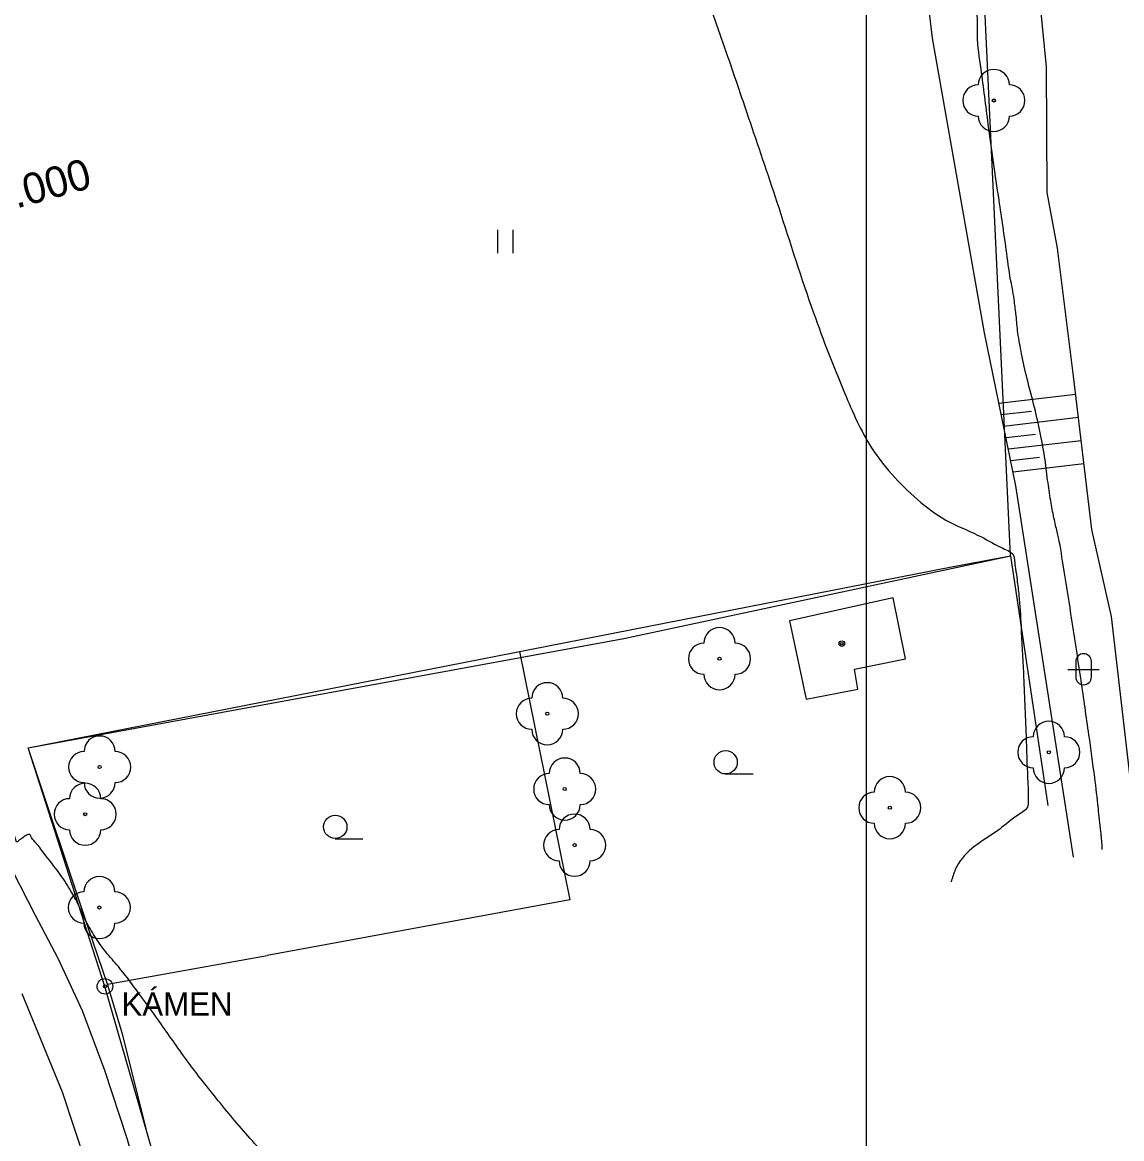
# Model space of a CAD drawing. Extents: x -478102 to -473059, y -1117705 to -1114104.
# Drawn here: x -476236.6 to -476165.9, y -1117156 to -1117084.2 of the extents above; entities that cross this region are included whole.
import ezdxf

# ---------------------------------------------------------------- set-up
doc = ezdxf.new("R2010")
doc.units = 0
for name, color, linetype in [('BodoveZnackySloupy', 7, 'Continuous'), ('Budovy', 7, 'Continuous'), ('cestn___p____kop_n__vrh', 7, 'Continuous'), ('HladinaVodnihoToku', 7, 'Continuous'), ('HranaTerennihoUtvaru', 7, 'Continuous'), ('ObPÚ', 7, 'Continuous'), ('Ploty', 7, 'Continuous'), ('POLYGONY_SITUACE_PF_POPISY', 7, 'Continuous'), ('PopisnaZnackaVyhybka', 7, 'Continuous'), ('PopisneZnackyKultura', 7, 'Continuous'), ('PopisObjektu', 7, 'Continuous'), ('RozhraniVozovky', 7, 'Continuous'), ('Teren_HranaSvahu', 7, 'Continuous'), ('Vrstevnice_hlavni', 7, 'Continuous'), ('Vrstevnice_vedlejsi', 7, 'Continuous'), ('VstupNaPozemek', 7, 'Continuous'), ('VyskoveSrafy', 7, 'Continuous'), ('ZnackyStromu', 7, 'Continuous')]:
    doc.layers.add(name, color=color, linetype=linetype)

msp = doc.modelspace()

# ---------------------------------------------------------------- linework, layer by layer
at = {"layer": 'BodoveZnackySloupy'}
for radius in [0.5, 0.1]:
    msp.add_circle((-476231.32, -1117146.23), radius, dxfattribs=at)
at = {"layer": 'Budovy'}
msp.add_lwpolyline([(-476179.82, -1117125.147), (-476180.599, -1117121.234), (-476187.275, -1117122.701), (-476186.207, -1117127.742), (-476182.873, -1117127.103), (-476183.091, -1117125.822)], close=True, dxfattribs=at)
at = {"layer": 'cestn___p____kop_n__vrh'}
msp.add_lwpolyline([(-476182.335, -1117180.282), (-476602.335, -1117180.282), (-476602.335, -1116586.282), (-476182.335, -1116586.282)], close=True, dxfattribs=at)
at = {"layer": 'HladinaVodnihoToku'}
msp.add_lwpolyline([(-476165.052, -1117135.383), (-476166.552, -1117122.432), (-476167.831, -1117116.835), (-476168.995, -1117106.978), (-476170.029, -1117098.738), (-476170.701, -1117095.145), (-476170.746, -1117087.056), (-476171.949, -1117074.832), (-476173.391, -1117070.652), (-476173.059, -1117068.741), (-476173.366, -1117065.264), (-476174.142, -1117057.395), (-476175.337, -1117045.193), (-476176.15, -1117036.518), (-476177.362, -1117031.476), (-476176.964, -1117029.141), (-476177.777, -1117025.659), (-476180.222, -1117017.465), (-476181.969, -1117010.204)], dxfattribs=at)
at = {"layer": 'HranaTerennihoUtvaru'}
msp.add_lwpolyline([(-476178.08, -1117085.22), (-476182.65, -1117046.23), (-476184.28, -1117024.06), (-476194.45, -1117027.03)], dxfattribs=at)
at = {"layer": 'ObPÚ'}
msp.add_lwpolyline([(-476159.5, -1117192.77), (-476224.13, -1117203.13), (-476225.41, -1117191.08), (-476226.67, -1117162.34), (-476231.32, -1117146.23), (-476236.27, -1117130.89), (-476197.93, -1117123.85), (-476173.05, -1117118.52), (-476175.07, -1117075.48), (-476185.89, -1117036.74), (-476189.59, -1117026.33), (-476192, -1117018.92), (-476203.93, -1116985.93)], dxfattribs=at)
at = {"layer": 'Ploty'}
for p, q in [((-476173.05, -1117118.52), (-476170.664, -1117134.589)), ((-476204.648, -1117124.689), (-476201.416, -1117140.657)), ((-476201.416, -1117140.657), (-476220.878, -1117144.236)), ((-476231.16, -1117146.08), (-476220.878, -1117144.236))]:
    msp.add_line(p, q, dxfattribs=at)
for points in [[(-476236.27, -1117130.89), (-476176.96, -1117119.26), (-476173.05, -1117118.52)], [(-476232.38, -1117142.5), (-476236.27, -1117130.89)], [(-476230.16, -1117149.36), (-476231.16, -1117146.08)]]:
    msp.add_lwpolyline(points, dxfattribs=at)
at = {"layer": 'PopisnaZnackaVyhybka'}
for radius in [0.18, 0.0797]:
    msp.add_circle((-476183.909, -1117124.176), radius, dxfattribs=at)
at = {"layer": 'PopisneZnackyKultura'}
for p, q in [((-476206.051, -1117099.044), (-476206.051, -1117097.544)), ((-476205.051, -1117099.044), (-476205.051, -1117097.544)), ((-476168.864, -1117125.331), (-476168.864, -1117126.331)), ((-476167.864, -1117125.331), (-476167.864, -1117126.331)), ((-476169.364, -1117125.831), (-476167.364, -1117125.831)), ((-476191.384, -1117132.551), (-476189.624, -1117132.551)), ((-476216.498, -1117136.728), (-476214.738, -1117136.728))]:
    msp.add_line(p, q, dxfattribs=at)
for centre in [(-476191.384, -1117131.811), (-476216.498, -1117135.968)]:
    msp.add_circle(centre, 0.75, dxfattribs=at)
for centre, start, end in [((-476168.356, -1117125.324), 0, 180), ((-476168.356, -1117126.324), 180, 0)]:
    msp.add_arc(centre, 0.5, start, end, dxfattribs=at)
at = {"layer": 'RozhraniVozovky'}
for points in [[(-476237.801, -1117137.737), (-476235.804, -1117141.64), (-476234.344, -1117144.407), (-476232.794, -1117147.784), (-476231.339, -1117151.616), (-476229.905, -1117155.995), (-476228.676, -1117160.384)], [(-476232.539, -1117157.584), (-476234.044, -1117153.045), (-476236.653, -1117146.701)]]:
    msp.add_lwpolyline(points, dxfattribs=at)
at = {"layer": 'Teren_HranaSvahu'}
for p, q in [((-476174.722, -1117104.178), (-476178.08, -1117085.22)), ((-476172.711, -1117114.033), (-476174.722, -1117104.178)), ((-476168.996, -1117137.921), (-476172.711, -1117114.033))]:
    msp.add_line(p, q, dxfattribs=at)
at = {"layer": 'Vrstevnice_hlavni'}
msp.add_spline([(-476206.652, -1117178.906), (-476206.912, -1117178.348), (-476209.341, -1117173.725), (-476211.536, -1117169.856), (-476213.496, -1117166.739), (-476215.223, -1117164.376), (-476216.372, -1117162.765), (-476216.944, -1117161.906), (-476216.939, -1117161.798), (-476216.948, -1117161.695), (-476216.97, -1117161.597), (-476217.006, -1117161.504), (-476217.035, -1117161.434), (-476217.055, -1117161.387), (-476217.068, -1117161.364), (-476217.869, -1117160.487), (-476219.458, -1117158.755), (-476221.836, -1117156.168), (-476224.025, -1117153.59), (-476226.026, -1117151.021), (-476227.839, -1117148.461), (-476229.316, -1117146.439), (-476230.458, -1117144.956), (-476231.265, -1117144.011), (-476231.967, -1117143.022), (-476232.564, -1117141.99), (-476233.057, -1117140.915), (-476233.666, -1117139.839), (-476234.391, -1117138.762), (-476235.231, -1117137.684), (-476235.806, -1117136.941), (-476236.117, -1117136.531), (-476236.162, -1117136.455), (-476236.279, -1117136.467), (-476236.468, -1117136.566), (-476236.728, -1117136.753), (-476236.903, -1117136.876), (-476236.994, -1117136.936), (-476237.001, -1117136.931), (-476237.008, -1117136.923), (-476237.014, -1117136.912), (-476237.021, -1117136.898), (-476237.036, -1117136.855), (-476237.059, -1117136.783), (-476237.089, -1117136.682), (-476237.266, -1117136.022), (-476237.588, -1117134.805), (-476238.057, -1117133.03), (-476238.423, -1117131.552), (-476238.688, -1117130.371), (-476238.85, -1117129.488), (-476238.979, -1117128.769), (-476239.073, -1117128.213), (-476239.134, -1117127.822), (-476239.32, -1117127.303), (-476239.632, -1117126.656), (-476240.07, -1117125.882), (-476240.487, -1117125.12), (-476240.885, -1117124.371), (-476241.262, -1117123.634), (-476241.579, -1117122.995), (-476241.836, -1117122.453), (-476242.033, -1117122.009), (-476242.251, -1117121.588), (-476242.49, -1117121.19), (-476242.749, -1117120.815), (-476243.08, -1117120.066), (-476243.481, -1117118.944), (-476243.953, -1117117.449), (-476244.291, -1117116.381), (-476244.494, -1117115.74), (-476244.561, -1117115.526), (-476244.665, -1117115.217), (-476244.806, -1117114.813), (-476244.984, -1117114.313), (-476245.236, -1117113.882), (-476245.562, -1117113.52), (-476245.962, -1117113.226), (-476246.483, -1117112.711), (-476247.125, -1117111.974), (-476247.888, -1117111.015), (-476248.249, -1117110.238), (-476248.209, -1117109.642), (-476247.766, -1117109.227), (-476247.681, -1117108.981), (-476247.952, -1117108.903), (-476248.581, -1117108.994), (-476249.094, -1117108.824), (-476249.493, -1117108.392)], degree=3, dxfattribs=at)
at = {"layer": 'Vrstevnice_vedlejsi'}
for points in [[(-476218.662, -1117033.435), (-476218.822, -1117034.635), (-476217.263, -1117036.911), (-476213.986, -1117040.265), (-476208.992, -1117044.695), (-476205.309, -1117047.877), (-476202.938, -1117049.809), (-476201.877, -1117050.493), (-476201.083, -1117050.788), (-476200.555, -1117050.695), (-476200.293, -1117050.212), (-476200.099, -1117049.847), (-476199.974, -1117049.597), (-476199.917, -1117049.464), (-476199.835, -1117049.37), (-476199.726, -1117049.313), (-476199.592, -1117049.295), (-476199.387, -1117049.198), (-476199.112, -1117049.021), (-476198.765, -1117048.765), (-476198.307, -1117048.409), (-476197.736, -1117047.953), (-476197.054, -1117047.397), (-476196.575, -1117047.173), (-476196.299, -1117047.28), (-476196.227, -1117047.719), (-476196.128, -1117048.519), (-476196.001, -1117049.68), (-476195.846, -1117051.202), (-476195.702, -1117052.674), (-476195.567, -1117054.097), (-476195.442, -1117055.471), (-476195.474, -1117056.701), (-476195.663, -1117057.787), (-476196.008, -1117058.731), (-476196.365, -1117059.696), (-476196.731, -1117060.685), (-476197.109, -1117061.695), (-476197.123, -1117063.752), (-476196.775, -1117066.855), (-476196.063, -1117071.005), (-476195.366, -1117074.361), (-476194.682, -1117076.923), (-476194.013, -1117078.692), (-476193.219, -1117080.86), (-476192.302, -1117083.427), (-476191.26, -1117086.392), (-476189.817, -1117090.625), (-476187.973, -1117096.125), (-476185.729, -1117102.894), (-476183.735, -1117108.045), (-476181.992, -1117111.578), (-476180.498, -1117113.494), (-476178.823, -1117115.088), (-476176.965, -1117116.361), (-476174.925, -1117117.312), (-476173.551, -1117118.042), (-476172.843, -1117118.55), (-476172.8, -1117118.837), (-476172.731, -1117119.351), (-476172.637, -1117120.093), (-476172.517, -1117121.062), (-476172.381, -1117123.052), (-476172.229, -1117126.063), (-476172.059, -1117130.096), (-476171.954, -1117132.864), (-476171.913, -1117134.367), (-476171.937, -1117134.606), (-476172.55, -1117135.185), (-476173.752, -1117136.105), (-476175.544, -1117137.365), (-476176.609, -1117138.711), (-476176.875, -1117139.506)], [(-476167.154, -1117137.424), (-476167.161, -1117137.225), (-476167.247, -1117136.247), (-476167.406, -1117134.768), (-476167.64, -1117132.789), (-476168.012, -1117130.045), (-476168.521, -1117126.535), (-476169.167, -1117122.259), (-476169.669, -1117119.115), (-476170.025, -1117117.1), (-476170.236, -1117116.217), (-476170.442, -1117115.129), (-476170.643, -1117113.838), (-476170.838, -1117112.343), (-476171.127, -1117110.728), (-476171.51, -1117108.993), (-476171.987, -1117107.138), (-476172.343, -1117105.532), (-476172.58, -1117104.177), (-476172.697, -1117103.072), (-476172.807, -1117102.176), (-476172.909, -1117101.489), (-476173.004, -1117101.011), (-476173.299, -1117099.062), (-476173.794, -1117095.642), (-476174.488, -1117090.75), (-476174.951, -1117087.207), (-476175.181, -1117085.013), (-476175.18, -1117084.167), (-476175.236, -1117083.188), (-476175.348, -1117082.077), (-476175.517, -1117080.833), (-476175.674, -1117079.86), (-476175.821, -1117079.16), (-476175.956, -1117078.731), (-476176.254, -1117076.34), (-476176.715, -1117071.985), (-476177.338, -1117065.667), (-476177.752, -1117061.381), (-476177.957, -1117059.126), (-476177.954, -1117058.902), (-476177.964, -1117058.642), (-476177.989, -1117058.344), (-476178.028, -1117058.009), (-476178.071, -1117057.621), (-476178.119, -1117057.181), (-476178.171, -1117056.687), (-476178.37, -1117054.109), (-476178.715, -1117049.446), (-476179.207, -1117042.699), (-476179.543, -1117038.092), (-476179.724, -1117035.627)], [(-476223.981, -1117207.237), (-476224.285, -1117206.855), (-476224.501, -1117206.557), (-476224.628, -1117206.343), (-476224.668, -1117206.213), (-476224.801, -1117205.902), (-476225.026, -1117205.411), (-476225.345, -1117204.739), (-476225.578, -1117204.261), (-476225.727, -1117203.975), (-476225.791, -1117203.883), (-476225.875, -1117203.662), (-476225.98, -1117203.311), (-476226.105, -1117202.831), (-476226.229, -1117202.417), (-476226.352, -1117202.067), (-476226.475, -1117201.782), (-476226.572, -1117201.501), (-476226.643, -1117201.224), (-476226.689, -1117200.951), (-476227.057, -1117200.755), (-476227.747, -1117200.637), (-476228.759, -1117200.595), (-476229.446, -1117200.566), (-476229.808, -1117200.548), (-476229.845, -1117200.544), (-476229.875, -1117200.547), (-476229.898, -1117200.559), (-476229.914, -1117200.578), (-476229.923, -1117200.586), (-476229.927, -1117200.583), (-476229.925, -1117200.567), (-476229.926, -1117200.55), (-476229.93, -1117200.533), (-476229.937, -1117200.515), (-476230.309, -1117199.985), (-476231.045, -1117198.942), (-476232.146, -1117197.387), (-476233.138, -1117195.885), (-476234.022, -1117194.438), (-476234.797, -1117193.044), (-476236.35, -1117190.18), (-476238.683, -1117185.847), (-476241.794, -1117180.043), (-476244.171, -1117175.438), (-476245.814, -1117172.033), (-476246.723, -1117169.826), (-476247.372, -1117168.01), (-476247.761, -1117166.585), (-476247.891, -1117165.55), (-476248.161, -1117164.525), (-476248.57, -1117163.508), (-476249.119, -1117162.501), (-476249.598, -1117161.498), (-476250.007, -1117160.498), (-476250.346, -1117159.503), (-476250.69, -1117158.53), (-476251.038, -1117157.58), (-476251.39, -1117156.652), (-476251.803, -1117155.599), (-476252.277, -1117154.423), (-476252.812, -1117153.123), (-476253.36, -1117151.76), (-476253.922, -1117150.336), (-476254.497, -1117148.85), (-476255.085, -1117147.257), (-476255.684, -1117145.558), (-476256.294, -1117143.752), (-476259.267, -1117141.777), (-476264.603, -1117139.631), (-476272.302, -1117137.316), (-476278.025, -1117135.721), (-476281.773, -1117134.847), (-476283.545, -1117134.694), (-476286.438, -1117134.211), (-476290.451, -1117133.398), (-476295.585, -1117132.255), (-476301.704, -1117130.929), (-476308.808, -1117129.42), (-476316.898, -1117127.729), (-476324.767, -1117125.966), (-476332.416, -1117124.134), (-476339.844, -1117122.232), (-476344.627, -1117120.838), (-476346.763, -1117119.952), (-476346.254, -1117119.574), (-476345.231, -1117118.402), (-476343.693, -1117116.434), (-476341.642, -1117113.672), (-476338.379, -1117110.142), (-476333.906, -1117105.844), (-476328.223, -1117100.779), (-476323.405, -1117096.497), (-476319.453, -1117093.001), (-476316.366, -1117090.289), (-476314.122, -1117087.639), (-476312.721, -1117085.051)]]:
    msp.add_spline(points, degree=3, dxfattribs=at)
at = {"layer": 'VstupNaPozemek'}
for p, q in [((-476231.16, -1117146.08), (-476232.38, -1117142.5)), ((-476228.67, -1117155.4), (-476230.16, -1117149.36))]:
    msp.add_line(p, q, dxfattribs=at)
at = {"layer": 'VyskoveSrafy'}
for p, q in [((-476173.799, -1117108.703), (-476168.86, -1117108.119)), ((-476173.648, -1117109.44), (-476171.698, -1117109.21)), ((-476173.498, -1117110.178), (-476168.684, -1117109.609)), ((-476173.347, -1117110.915), (-476171.447, -1117110.691)), ((-476173.197, -1117111.652), (-476168.508, -1117111.099)), ((-476173.046, -1117112.39), (-476171.196, -1117112.171)), ((-476172.896, -1117113.127), (-476168.332, -1117112.588))]:
    msp.add_line(p, q, dxfattribs=at)
at = {"layer": 'ZnackyStromu'}
for centre in [(-476174.131, -1117089.228), (-476191.781, -1117125.147), (-476202.859, -1117128.689), (-476170.593, -1117131.169), (-476231.66, -1117132.12), (-476201.736, -1117133.536), (-476180.824, -1117134.734), (-476232.59, -1117135.153), (-476201.104, -1117137.144), (-476231.678, -1117141.157)]:
    msp.add_circle(centre, 0.1, dxfattribs=at)
for centre, start, end in [((-476174.131, -1117088.228), 0, 180), ((-476175.131, -1117089.228), 90, 270), ((-476173.131, -1117089.228), 270, 90), ((-476174.131, -1117090.228), 180, 0), ((-476191.781, -1117124.147), 0, 180), ((-476192.781, -1117125.147), 90, 270), ((-476190.781, -1117125.147), 270, 90), ((-476202.859, -1117127.689), 0, 180), ((-476191.781, -1117126.147), 180, 0), ((-476203.859, -1117128.689), 90, 270), ((-476201.859, -1117128.689), 270, 90), ((-476170.593, -1117130.169), 0, 180), ((-476231.66, -1117131.12), 0, 180), ((-476202.859, -1117129.689), 180, 0), ((-476171.593, -1117131.169), 90, 270), ((-476169.593, -1117131.169), 270, 90), ((-476232.66, -1117132.12), 90, 270), ((-476230.66, -1117132.12), 270, 90), ((-476201.736, -1117132.536), 0, 180), ((-476202.736, -1117133.536), 90, 270), ((-476200.736, -1117133.536), 270, 90), ((-476170.593, -1117132.169), 180, 0), ((-476232.59, -1117134.153), 0, 180), ((-476231.66, -1117133.12), 180, 0), ((-476180.824, -1117133.734), 0, 180), ((-476181.824, -1117134.734), 90, 270), ((-476179.824, -1117134.734), 270, 90), ((-476233.59, -1117135.153), 90, 270), ((-476231.59, -1117135.153), 270, 90), ((-476201.736, -1117134.536), 180, 0), ((-476201.104, -1117136.144), 0, 180), ((-476180.824, -1117135.734), 180, 0), ((-476232.59, -1117136.153), 180, 0), ((-476202.104, -1117137.144), 90, 270), ((-476200.104, -1117137.144), 270, 90), ((-476201.104, -1117138.144), 180, 0), ((-476231.678, -1117140.157), 0, 180), ((-476232.678, -1117141.157), 90, 270), ((-476230.678, -1117141.157), 270, 90), ((-476231.678, -1117142.157), 180, 0)]:
    msp.add_arc(centre, 1, start, end, dxfattribs=at)

# ---------------------------------------------------------------- texts
at = {"layer": 'POLYGONY_SITUACE_PF_POPISY'}
msp.add_text('KM=0.000', height=1.9765, rotation=15.49633, dxfattribs=at).set_placement((-476243.739, -1117098.054))
at = {"layer": 'PopisObjektu'}
msp.add_text('KÁMEN', height=1.5, dxfattribs=at).set_placement((-476230.251, -1117148.116))

doc.saveas('drawing.dxf')
